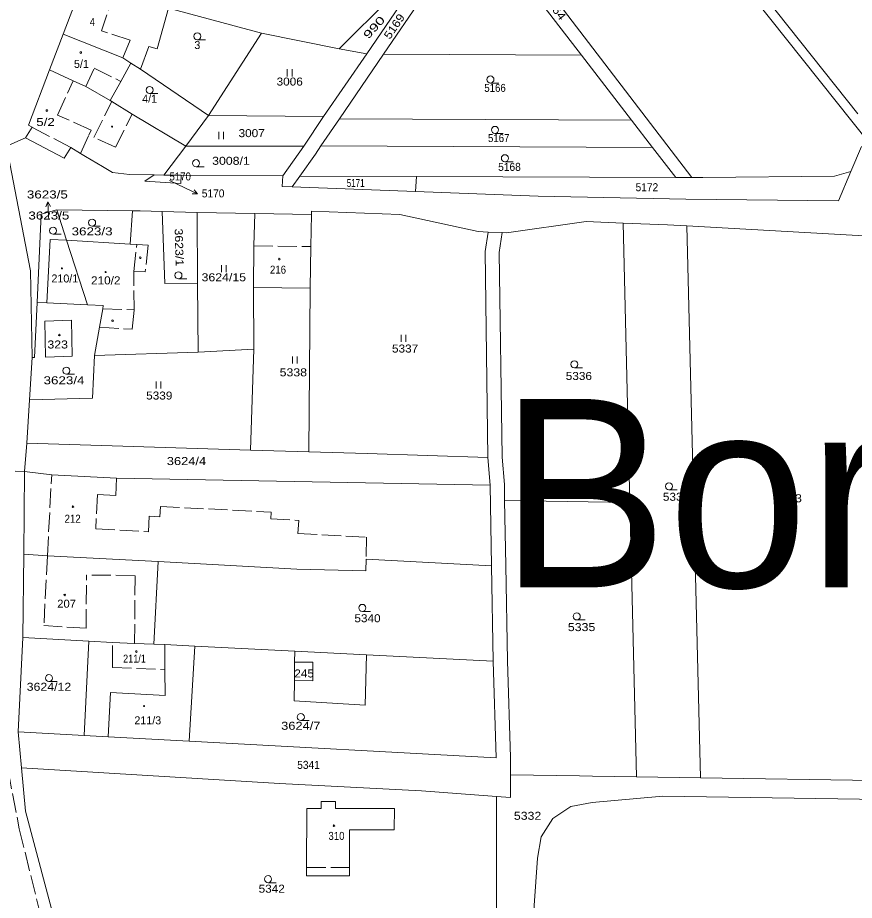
# Model space of a CAD drawing. Extents: x -590528 to -586543, y -1119609 to -1116685.
# Drawn here: x -588671 to -588493.4, y -1118717.9 to -1118530.4 of the extents above; entities that cross this region are included whole.
import ezdxf
from ezdxf.enums import TextEntityAlignment as Align

# ---------------------------------------------------------------- set-up
doc = ezdxf.new("R2010")
doc.units = 0
doc.header["$LTSCALE"] = 0.68
doc.linetypes.add('LONG_DASHED', pattern=[7.5, 6, -1.5])
for name, color, linetype, lineweight in [('1', 7, 'Continuous', 13), ('2', 7, 'LONG_DASHED', 13), ('3', 7, 'Continuous', 13), ('6', 7, 'Continuous', 13)]:
    doc.layers.add(name, color=color, linetype=linetype, lineweight=lineweight)
doc.layers.add('5', color=7, linetype='Continuous')

msp = doc.modelspace()

# ---------------------------------------------------------------- linework, layer by layer
at = {"layer": '1'}
for p, q in [((-588492.66, -1118550.88), (-588543.11, -1118487.4)), ((-588544.44, -1118488.93), (-588490.36, -1118556.97)), ((-588593.32, -1118538.22), (-588573.68, -1118509.4)), ((-588602.77, -1118537.06), (-588582.21, -1118516.58)), ((-588582.21, -1118516.58), (-588596.88, -1118538.12)), ((-588638.94, -1118528.43), (-588641.38, -1118537.05)), ((-588638.94, -1118528.43), (-588619.25, -1118533.72)), ((-588664.19, -1118541.56), (-588661.33, -1118533.96)), ((-588619.25, -1118533.72), (-588630.46, -1118551.23)), ((-588643.11, -1118536.56), (-588644.91, -1118541.39)), ((-588643.11, -1118536.56), (-588641.38, -1118537.05)), ((-588602.69, -1118551.95), (-588593.32, -1118538.22)), ((-588551.33, -1118538.42), (-588593.32, -1118538.22)), ((-588646.93, -1118540.08), (-588644.91, -1118541.39)), ((-588668.63, -1118553.29), (-588664.19, -1118541.56)), ((-588656.53, -1118545.05), (-588651.35, -1118548.06)), ((-588646.64, -1118550.91), (-588635.31, -1118557.76)), ((-588606.07, -1118551.44), (-588630.46, -1118551.23)), ((-588606.61, -1118557.68), (-588602.69, -1118551.95)), ((-588669.33, -1118556), (-588667.86, -1118553.7)), ((-588667.86, -1118553.7), (-588668.63, -1118553.29)), ((-588673.36, -1118557.76), (-588668.24, -1118584.17)), ((-588635.31, -1118557.76), (-588639.92, -1118563.86)), ((-588659.67, -1118558.05), (-588661.07, -1118560.26)), ((-588656.58, -1118559.9), (-588652.93, -1118562.08)), ((-588650.86, -1118563.29), (-588652.93, -1118562.08)), ((-588642.02, -1118563.82), (-588643.96, -1118565.2)), ((-588586.36, -1118564.18), (-588531.31, -1118564.39)), ((-588666.84, -1118590.93), (-588665.96, -1118572.14)), ((-588665.96, -1118572.14), (-588662.66, -1118571.27)), ((-588662.66, -1118571.27), (-588660.57, -1118577.72)), ((-588646.56, -1118571.45), (-588647.11, -1118578.51)), ((-588640.28, -1118571.6), (-588644.98, -1118571.47)), ((-588640.28, -1118571.6), (-588639.76, -1118586.88)), ((-588632.9, -1118571.8), (-588640.28, -1118571.6)), ((-588632.9, -1118571.8), (-588620.63, -1118572)), ((-588620.63, -1118572), (-588608.64, -1118572.21)), ((-588542.49, -1118574.05), (-588541.04, -1118633.38)), ((-588542.49, -1118574.05), (-588533.04, -1118574.41)), ((-588533.04, -1118574.41), (-588528.96, -1118574.64)), ((-588490.11, -1118576.85), (-588528.96, -1118574.64)), ((-588528.96, -1118574.64), (-588526.08, -1118691.83)), ((-588568.14, -1118576.07), (-588571.16, -1118575.96)), ((-588664.07, -1118577.56), (-588664.77, -1118591.03)), ((-588664.07, -1118577.56), (-588660.57, -1118577.72)), ((-588660.57, -1118577.72), (-588656.16, -1118591.44)), ((-588647.11, -1118578.51), (-588660.57, -1118577.72)), ((-588668.24, -1118584.17), (-588667.88, -1118602.6)), ((-588639.76, -1118586.88), (-588632.77, -1118586.81)), ((-588608.93, -1118587.9), (-588620.94, -1118587.76)), ((-588608.93, -1118587.9), (-588609.17, -1118622.63)), ((-588666.84, -1118590.93), (-588664.77, -1118591.03)), ((-588664.77, -1118591.03), (-588656.16, -1118591.44)), ((-588652.92, -1118592.24), (-588653.6, -1118596.18)), ((-588653.6, -1118596.18), (-588654.63, -1118602.16)), ((-588620.88, -1118600.81), (-588621.54, -1118622.25)), ((-588654.63, -1118602.16), (-588655.06, -1118611.24)), ((-588632.66, -1118601.45), (-588654.63, -1118602.16)), ((-588668.43, -1118611.58), (-588655.06, -1118611.24)), ((-588668.99, -1118620.78), (-588669.51, -1118626.8)), ((-588668.99, -1118620.78), (-588621.54, -1118622.25)), ((-588621.54, -1118622.25), (-588609.17, -1118622.63)), ((-588669.51, -1118626.8), (-588671.52, -1118626.71)), ((-588669.66, -1118644.36), (-588669.51, -1118626.8)), ((-588663.73, -1118627.51), (-588669.51, -1118626.8)), ((-588663.73, -1118627.51), (-588649.96, -1118628.25)), ((-588649.96, -1118628.25), (-588570.69, -1118629.73)), ((-588541.04, -1118633.38), (-588539.62, -1118691.62)), ((-588669.83, -1118662.08), (-588669.66, -1118644.36)), ((-588664.66, -1118644.68), (-588669.66, -1118644.36)), ((-588664.66, -1118644.68), (-588641.17, -1118645.89)), ((-588597.01, -1118645.45), (-588597.1, -1118647.89)), ((-588570.4, -1118646.81), (-588597.01, -1118645.45)), ((-588597.1, -1118647.89), (-588611.75, -1118647.53)), ((-588570.05, -1118667.06), (-588570.4, -1118646.81)), ((-588670.83, -1118682.05), (-588669.83, -1118662.08)), ((-588656.82, -1118682.87), (-588655.87, -1118662.84)), ((-588639.71, -1118668.88), (-588639.71, -1118663.56)), ((-588634.54, -1118684.07), (-588633.36, -1118663.88)), ((-588597.19, -1118676.39), (-588596.92, -1118665.71)), ((-588639.71, -1118668.88), (-588639.65, -1118674.35)), ((-588612.3, -1118675.48), (-588597.19, -1118676.39)), ((-588670.18, -1118689.74), (-588670.83, -1118682.05)), ((-588634.54, -1118684.07), (-588651.76, -1118683.16)), ((-588670.18, -1118689.74), (-588669.27, -1118698.89)), ((-588615.43, -1118693.07), (-588670.18, -1118689.74)), ((-588526.08, -1118691.83), (-588487.26, -1118692.42)), ((-588566.39, -1118696.02), (-588569.35, -1118695.79))]:
    msp.add_line(p, q, dxfattribs=at)
for points in [[(-588525.61, -1118564.4), (-588527.9, -1118564.4), (-588579.6, -1118496.72)], [(-588661.33, -1118533.96), (-588657.05, -1118522.74), (-588651.31, -1118507.67)], [(-588573.68, -1118509.4), (-588551.33, -1118538.42), (-588540.68, -1118552.23), (-588602.69, -1118551.95)], [(-588661.33, -1118533.96), (-588648.66, -1118538.96), (-588646.93, -1118540.08)], [(-588619.25, -1118533.72), (-588602.77, -1118537.06), (-588596.88, -1118538.12)], [(-588596.88, -1118538.12), (-588606.07, -1118551.44), (-588610.26, -1118557.71)], [(-588651.35, -1118548.06), (-588649.1, -1118543.99), (-588646.93, -1118540.08)], [(-588664.19, -1118541.56), (-588659.16, -1118543.85), (-588656.53, -1118545.05)], [(-588644.91, -1118541.39), (-588630.46, -1118551.23), (-588635.31, -1118557.76), (-588610.26, -1118557.71)], [(-588651.35, -1118548.06), (-588650.98, -1118548.28), (-588646.64, -1118550.91)], [(-588540.68, -1118552.23), (-588536.23, -1118558), (-588606.61, -1118557.68)], [(-588661.07, -1118560.26), (-588669.33, -1118556), (-588673.36, -1118557.76)], [(-588610.26, -1118557.71), (-588614.72, -1118564.06), (-588636.29, -1118563.91)], [(-588614.72, -1118564.06), (-588614.81, -1118566.29), (-588612.68, -1118566.37), (-588611.07, -1118564.09), (-588607.79, -1118559.42), (-588606.61, -1118557.68)], [(-588491.93, -1118557.83), (-588494.2, -1118563.14), (-588497.63, -1118564.09), (-588525.61, -1118564.4)], [(-588659.67, -1118558.05), (-588657.62, -1118559.28), (-588656.58, -1118559.9)], [(-588536.23, -1118558), (-588531.31, -1118564.39), (-588527.9, -1118564.4)], [(-588642.02, -1118563.82), (-588647.24, -1118563.72), (-588650.86, -1118563.29)], [(-588529.18, -1118569), (-588496.77, -1118569.33), (-588494.2, -1118563.14)], [(-588643.96, -1118565.2), (-588636.34, -1118565.67), (-588636.29, -1118563.91)], [(-588636.29, -1118563.91), (-588636.8, -1118563.91), (-588639.92, -1118563.86), (-588642.02, -1118563.82)], [(-588612.68, -1118566.37), (-588586.52, -1118567.37), (-588586.36, -1118564.18), (-588611.07, -1118564.09)], [(-588586.52, -1118567.37), (-588560.51, -1118568.36), (-588529.18, -1118569)], [(-588644.98, -1118571.47), (-588646.56, -1118571.45), (-588662.66, -1118571.27)], [(-588632.66, -1118601.45), (-588632.77, -1118586.81), (-588632.9, -1118571.8)], [(-588620.63, -1118572), (-588620.88, -1118578.89), (-588620.94, -1118587.76)], [(-588608.64, -1118572.21), (-588608.77, -1118579.07), (-588608.93, -1118587.9)], [(-588573.25, -1118575.88), (-588589.84, -1118572.24), (-588608.61, -1118571.53), (-588608.64, -1118572.21)], [(-588568.18, -1118623.73), (-588568.77, -1118580.31), (-588568.14, -1118576.07), (-588567.26, -1118576.11), (-588550.32, -1118573.75), (-588542.49, -1118574.05)], [(-588571.18, -1118623.85), (-588571.77, -1118580.11), (-588571.16, -1118575.96), (-588573.25, -1118575.88)], [(-588620.94, -1118587.76), (-588620.88, -1118600.81), (-588632.66, -1118601.45)], [(-588666.84, -1118590.93), (-588667.38, -1118602.6), (-588667.88, -1118602.6)], [(-588656.16, -1118591.44), (-588652.81, -1118591.57), (-588652.92, -1118592.24)], [(-588667.88, -1118602.6), (-588668.43, -1118611.58), (-588668.99, -1118620.78)], [(-588609.17, -1118622.63), (-588596.79, -1118623.01), (-588571.18, -1118623.85), (-588570.69, -1118629.73), (-588570.4, -1118646.81)], [(-588541.04, -1118633.38), (-588567.63, -1118632.97), (-588567.69, -1118629.58), (-588568.18, -1118623.73)], [(-588566.4, -1118691.22), (-588566.41, -1118687.52), (-588567.05, -1118666.98), (-588567.4, -1118646.76), (-588567.63, -1118632.97)], [(-588611.75, -1118647.53), (-588641.17, -1118645.89), (-588642.06, -1118663.44)], [(-588669.83, -1118662.08), (-588655.87, -1118662.84), (-588650.87, -1118663.11)], [(-588650.87, -1118663.11), (-588646.16, -1118663.29), (-588642.06, -1118663.44)], [(-588642.06, -1118663.44), (-588639.71, -1118663.56), (-588633.36, -1118663.88)], [(-588570.05, -1118667.06), (-588596.92, -1118665.71), (-588612.17, -1118664.94), (-588633.36, -1118663.88)], [(-588612.17, -1118664.94), (-588612.2, -1118667.27), (-588612.25, -1118671.17), (-588612.3, -1118675.48)], [(-588570.05, -1118667.06), (-588569.41, -1118687.57), (-588634.54, -1118684.07)], [(-588651.76, -1118683.16), (-588651.24, -1118673.73), (-588639.65, -1118674.35)], [(-588651.76, -1118683.16), (-588656.82, -1118682.87), (-588670.83, -1118682.05)], [(-588526.08, -1118691.83), (-588539.62, -1118691.62), (-588548.98, -1118691.48), (-588551.76, -1118691.44), (-588566.4, -1118691.22), (-588566.39, -1118696.02)], [(-588569.35, -1118695.79), (-588585.28, -1118694.57), (-588615.43, -1118693.07)], [(-588660.52, -1118731.91), (-588569.63, -1118740.9), (-588569.39, -1118720.67), (-588569.35, -1118705.67), (-588569.35, -1118695.79)], [(-588534.05, -1118695.71), (-588549.07, -1118697.08), (-588553.57, -1118697.94), (-588557.37, -1118700.49), (-588559.86, -1118704.34), (-588560.64, -1118708.91), (-588561.74, -1118723.95), (-588558.91, -1118809.84)], [(-588483.64, -1118846.11), (-588487.68, -1118696.41), (-588534.05, -1118695.71)], [(-588669.27, -1118698.89), (-588660.52, -1118731.91), (-588651.24, -1118758.54), (-588647.59, -1118770.04), (-588644.36, -1118781.65)]]:
    msp.add_lwpolyline(points, dxfattribs=at)
for points in [[(-588665.02, -1118602.52), (-588665.23, -1118594.88), (-588659.57, -1118594.71), (-588659.36, -1118602.32)], [(-588609.6, -1118698.33), (-588609.64, -1118710.86), (-588609.65, -1118712.66), (-588600.57, -1118712.62), (-588600.56, -1118710.88), (-588600.52, -1118702.85), (-588591.05, -1118702.9), (-588590.98, -1118698.37), (-588603.54, -1118698.34), (-588603.54, -1118696.85), (-588606.53, -1118696.84), (-588606.53, -1118698.34)]]:
    msp.add_lwpolyline(points, close=True, dxfattribs=at)
at = {"layer": '2'}
for p, q in [((-588650.42, -1118524.99), (-588653.17, -1118533.24)), ((-588647.07, -1118535.25), (-588653.17, -1118533.24)), ((-588648.66, -1118538.96), (-588647.07, -1118535.25)), ((-588662.48, -1118551.13), (-588659.16, -1118543.85)), ((-588654.83, -1118555.86), (-588650.98, -1118548.28)), ((-588655.38, -1118554.36), (-588662.48, -1118551.13)), ((-588650.21, -1118557.96), (-588646.64, -1118550.91)), ((-588659.67, -1118558.05), (-588667.86, -1118553.7)), ((-588657.62, -1118559.28), (-588655.85, -1118555.39)), ((-588655.85, -1118555.39), (-588655.38, -1118554.36)), ((-588650.21, -1118557.96), (-588654.83, -1118555.86)), ((-588620.88, -1118578.89), (-588608.77, -1118579.07)), ((-588652.92, -1118592.24), (-588646.23, -1118592.49)), ((-588664.66, -1118644.68), (-588663.73, -1118627.51)), ((-588664.66, -1118644.68), (-588665.4, -1118659.53)), ((-588656.44, -1118660.09), (-588656.36, -1118648.79)), ((-588656.44, -1118660.09), (-588665.4, -1118659.53)), ((-588650.86, -1118668.41), (-588639.71, -1118668.88)), ((-588608.3, -1118667.32), (-588612.2, -1118667.27)), ((-588608.35, -1118671.22), (-588608.3, -1118667.32)), ((-588612.25, -1118671.17), (-588608.35, -1118671.22)), ((-588673.01, -1118690.19), (-588670.62, -1118702.66)), ((-588670.62, -1118702.66), (-588665.95, -1118721.6)), ((-588609.64, -1118710.86), (-588600.56, -1118710.88))]:
    msp.add_line(p, q, dxfattribs=at)
for points in [[(-588656.53, -1118545.05), (-588654.71, -1118541.18), (-588649.1, -1118543.99)], [(-588647.11, -1118578.51), (-588645.67, -1118578.59), (-588643.27, -1118578.77), (-588643.88, -1118584.4), (-588646.33, -1118584.32), (-588645.67, -1118578.59)], [(-588653.6, -1118596.18), (-588646.69, -1118596.59), (-588646.23, -1118592.49), (-588646.33, -1118584.32)], [(-588649.96, -1118628.25), (-588650.15, -1118631.89), (-588654, -1118631.69), (-588654.39, -1118638.97), (-588643.21, -1118639.58), (-588643.03, -1118636.28), (-588640.78, -1118636.4)], [(-588640.78, -1118636.4), (-588640.66, -1118634.21), (-588617.2, -1118635.47), (-588617.27, -1118636.87), (-588611.33, -1118637.19), (-588611.48, -1118639.98), (-588596.91, -1118640.77), (-588597.01, -1118645.45)], [(-588646.16, -1118663.29), (-588646.06, -1118648.87), (-588656.36, -1118648.79)], [(-588650.86, -1118668.41), (-588650.87, -1118667.83), (-588650.87, -1118663.11)]]:
    msp.add_lwpolyline(points, dxfattribs=at)
at = {"layer": '3'}
for p, q in [((-588638.77, -1118565.01), (-588635.52, -1118566.57)), ((-588632.814, -1118567.865), (-588635.52, -1118566.57)), ((-588664.57, -1118569.585), (-588664.39, -1118572.58)), ((-588664.34, -1118573.31), (-588664.39, -1118572.58))]:
    msp.add_line(p, q, dxfattribs=at)
for points in [[(-588633.5, -1118566.984), (-588632.814, -1118567.865), (-588633.933, -1118567.885)], [(-588665.008, -1118570.613), (-588664.57, -1118569.585), (-588664.01, -1118570.554)]]:
    msp.add_lwpolyline(points, dxfattribs=at)
at = {"layer": '6'}
for p, q in [((-588632.84, -1118535.16), (-588631.09, -1118535.16)), ((-588613.74, -1118542.92), (-588613.74, -1118541.42)), ((-588612.74, -1118542.92), (-588612.74, -1118541.42)), ((-588570.64, -1118544.33), (-588568.89, -1118544.33)), ((-588642.96, -1118546.56), (-588641.21, -1118546.56)), ((-588628.3, -1118556.22), (-588628.3, -1118554.72)), ((-588627.3, -1118556.22), (-588627.3, -1118554.72)), ((-588569.68, -1118555.03), (-588567.93, -1118555.03)), ((-588567.58, -1118561.05), (-588565.83, -1118561.05)), ((-588633.11, -1118562.1), (-588631.36, -1118562.1)), ((-588655.17, -1118574.72), (-588653.42, -1118574.72)), ((-588663.45, -1118576.43), (-588661.7, -1118576.43)), ((-588627.72, -1118584.47), (-588627.72, -1118582.97)), ((-588626.72, -1118584.47), (-588626.72, -1118582.97)), ((-588636.85, -1118585.9), (-588635.1, -1118585.9)), ((-588589.62, -1118599.26), (-588589.62, -1118597.76)), ((-588588.62, -1118599.26), (-588588.62, -1118597.76)), ((-588612.67, -1118603.91), (-588612.67, -1118602.41)), ((-588611.67, -1118603.91), (-588611.67, -1118602.41)), ((-588552.84, -1118604.8), (-588551.09, -1118604.8)), ((-588660.62, -1118606.14), (-588658.87, -1118606.14)), ((-588641.59, -1118609.17), (-588641.59, -1118607.67)), ((-588640.59, -1118609.17), (-588640.59, -1118607.67)), ((-588532.76, -1118630.7), (-588531.01, -1118630.7)), ((-588508.2, -1118631.19), (-588506.45, -1118631.19)), ((-588597.82, -1118656.51), (-588596.07, -1118656.51)), ((-588552.32, -1118658.33), (-588550.57, -1118658.33)), ((-588664.32, -1118671.41), (-588662.57, -1118671.41)), ((-588610.88, -1118679.69), (-588609.13, -1118679.69)), ((-588617.83, -1118714.1), (-588616.08, -1118714.1))]:
    msp.add_line(p, q, dxfattribs=at)
for centre, radius in [((-588632.84, -1118534.41), 0.75), ((-588657.5702, -1118537.8604), 0.175), ((-588570.64, -1118543.58), 0.75), ((-588642.96, -1118545.81), 0.75), ((-588664.7602, -1118550.1704), 0.175), ((-588650.9201, -1118553.5902), 0.1172), ((-588569.68, -1118554.28), 0.75), ((-588567.58, -1118560.3), 0.75), ((-588633.11, -1118561.35), 0.75), ((-588655.17, -1118573.97), 0.75), ((-588663.45, -1118575.68), 0.75), ((-588644.9402, -1118581.4304), 0.175), ((-588615.4402, -1118581.7104), 0.175), ((-588661.5701, -1118583.6802), 0.1172), ((-588652.2901, -1118584.4702), 0.1172), ((-588636.85, -1118585.15), 0.75), ((-588650.8302, -1118594.7904), 0.175), ((-588662.1102, -1118597.8304), 0.175), ((-588660.62, -1118605.39), 0.75), ((-588552.84, -1118604.05), 0.75), ((-588532.76, -1118629.95), 0.75), ((-588508.2, -1118630.44), 0.75), ((-588659.2202, -1118634.2804), 0.175), ((-588660.9802, -1118653.0204), 0.175), ((-588597.82, -1118655.76), 0.75), ((-588552.32, -1118657.58), 0.75), ((-588645.7702, -1118665.0304), 0.175), ((-588664.32, -1118670.66), 0.75), ((-588644.1401, -1118676.6102), 0.1172), ((-588610.88, -1118678.94), 0.75), ((-588603.8502, -1118702.0104), 0.175), ((-588617.83, -1118713.35), 0.75)]:
    msp.add_circle(centre, radius, dxfattribs=at)

# ---------------------------------------------------------------- texts
at = {"layer": '3'}
for s, rotation, width, p in [('5164', 307.736, 1.2, (-588559.545, -1118526.378)), ('5169', 55.749, 1.15, (-588591.986, -1118535.174))]:
    msp.add_text(s, height=1.7, rotation=rotation, dxfattribs=dict(at, width=width)).set_placement(p)
for s, width, p in [('4', 0.9, (-588655.1105, -1118532.21)), ('3006', 1.1, (-588613.2405, -1118544.87)), ('5/2', 1.25, (-588665.05, -1118553.46)), ('3007', 1.1, (-588621.3105, -1118555.82)), ('3008/1', 1.15, (-588625.7005, -1118561.69)), ('3623/5', 1.25, (-588664.6605, -1118568.84)), ('3623/5', 1.25, (-588664.34, -1118573.31)), ('3623/3', 1.25, (-588655.17, -1118576.67)), ('216', 0.9, (-588615.7205, -1118584.8)), ('210/2', 1.1, (-588652.27, -1118587.08)), ('3624/15', 1.15, (-588627.22, -1118586.42)), ('323', 1.15, (-588662.4705, -1118600.69)), ('3623/4', 1.25, (-588661.12, -1118608.29)), ('3624/4', 1.2, (-588635.14, -1118625.44)), ('212', 0.9, (-588659.3, -1118637.68)), ('207', 1.05, (-588660.58, -1118655.72)), ('211/1', 0.85, (-588646.1705, -1118667.38)), ('245', 1.1, (-588610.1795, -1118670.53)), ('3624/12', 1.15, (-588664.32, -1118673.36)), ('3624/7', 1.2, (-588610.8805, -1118681.64))]:
    msp.add_text(s, height=1.7, dxfattribs=dict(at, width=width)).set_placement(p, align=Align.CENTER)
for s, rotation, width, p in [('990', 48.014, 1.45, (-588594.7083, -1118533.0911)), ('3623/1', 271.697, 1.15, (-588637.5292, -1118579.2353))]:
    msp.add_text(s, height=1.7, rotation=rotation, dxfattribs=dict(at, width=width)).set_placement(p, align=Align.CENTER)
for s, p in [('3', (-588632.8405, -1118537.11)), ('5/1', (-588657.43, -1118541.12)), ('4/1', (-588642.9605, -1118548.51)), ('210/1', (-588660.951, -1118586.67)), ('211/3', (-588643.3505, -1118680.49))]:
    msp.add_text(s, height=1.7, dxfattribs=at).set_placement(p, align=Align.CENTER)
for s, width, p in [('5166', 0.9, (-588571.943, -1118546.21)), ('5167', 0.9, (-588571.163, -1118556.86)), ('5168', 0.95, (-588569.003, -1118562.98)), ('5170', 0.9, (-588638.746, -1118565.01)), ('5171', 0.75, (-588601.143, -1118566.41)), ('5170', 0.95, (-588631.893, -1118568.61)), ('5172', 0.95, (-588539.843, -1118567.3)), ('5337', 1.1, (-588591.533, -1118601.55)), ('5338', 1.15, (-588615.373, -1118606.6)), ('5336', 1.1, (-588554.663, -1118607.37)), ('5339', 1.1, (-588643.693, -1118611.53)), ('5334', 1.1, (-588534.053, -1118633.02)), ('5333', 1.15, (-588510.373, -1118633.34)), ('5340', 1.1, (-588599.513, -1118658.81)), ('5335', 1.15, (-588554.213, -1118660.69)), ('5341', 0.95, (-588611.643, -1118689.94)), ('5332', 1.15, (-588565.673, -1118700.75)), ('310', 0.9, (-588605.023, -1118705.02)), ('5342', 1.1, (-588619.833, -1118716.23))]:
    msp.add_text(s, height=1.7, dxfattribs=dict(at, width=width)).set_placement(p)
at = {"layer": '5'}
msp.add_text('Borotín', height=40, dxfattribs=at).set_placement((-588568.687, -1118651.406))

doc.saveas('drawing.dxf')
